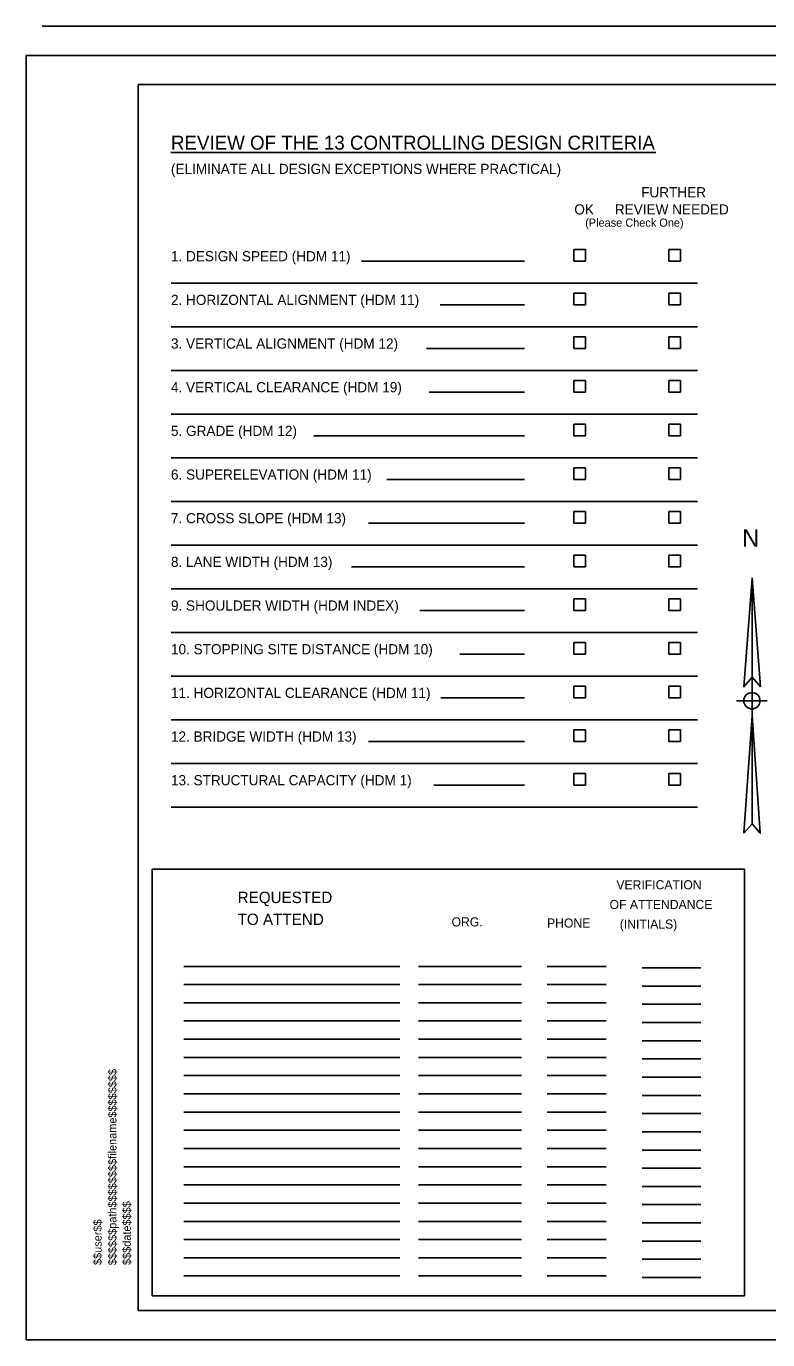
# Model space of a CAD drawing. Extents: x -796 to 2793, y -4650 to 4425.
# Drawn here: x 986 to 1622, y 2150 to 3275 of the extents above; entities that cross this region are included whole.
import ezdxf

# ---------------------------------------------------------------- set-up
doc = ezdxf.new("R2010")
doc.units = 0
for name, color, linetype in [('RD_EX_Misc', 7, 'Continuous'), ('RD_HC_CL', 7, 'Continuous'), ('RD_HC_Data', 7, 'Continuous'), ('RD_HC_Data_Tic', 7, 'Continuous'), ('RD_TX_Misc1', 7, 'Continuous')]:
    doc.layers.add(name, color=color, linetype=linetype)

msp = doc.modelspace()

# ---------------------------------------------------------------- linework, layer by layer
at = {"layer": 'RD_EX_Misc'}
for p, q in [((1608.2, 2802.4), (1601.2, 2709.1)), ((1608.2, 2802.4), (1615.4, 2709.1)), ((1608.2, 2802.4), (1608.2, 2591.7)), ((1608.2, 2717.6), (1601.2, 2709.1)), ((1608.2, 2717.6), (1615.4, 2709.1)), ((1594.9, 2697.3), (1621.3, 2697.3)), ((1608.2, 2684.7), (1601.3, 2583.8)), ((1608.2, 2684.7), (1615.3, 2583.8)), ((1601.3, 2583.8), (1608.2, 2591.9)), ((1615.3, 2583.8), (1608.2, 2591.9))]:
    msp.add_line(p, q, dxfattribs=at)
for points in [[(1608.2, 2717.6), (1608.2, 2802.4), (1601.2, 2709.1), (1608.2, 2717.6)], [(1608.2, 2697.3), (1608.2, 2704.3)], [(1601.1, 2697.3), (1608.2, 2697.3)], [(1608.2, 2697.3), (1608.2, 2690.3)], [(1615.1, 2697.3), (1608.2, 2697.3)], [(1608.2, 2684.7), (1608.2, 2591.8), (1608.2, 2591.9), (1615.3, 2583.8), (1608.2, 2684.7)]]:
    msp.add_lwpolyline(points, dxfattribs=at)
for start, end in [(89.5907, 180), (89.5907, 180), (0, 89.5907), (180, 270.4093), (270.4093, 0), (270.4093, 0)]:
    msp.add_arc((1608.1, 2697.3), 7, start, end, dxfattribs=at)
at = {"layer": 'RD_HC_CL'}
msp.add_lwpolyline([(986.4, 3250), (2782.4, 3250), (2782.4, 2150), (986.4, 2150)], close=True, dxfattribs=at)
at = {"layer": 'RD_HC_Data'}
for p, q in [((2760, 3275), (1000, 3275)), ((2760, 3275), (1000, 3275)), ((2760, 3250), (1000, 3250)), ((1525.9, 3166.8), (1110.2, 3166.8)), ((1465.5, 3083.7), (1455.5, 3083.7)), ((1455.5, 3073.7), (1455.5, 3083.7)), ((1465.5, 3073.7), (1465.5, 3083.7)), ((1547, 3083.7), (1537, 3083.7)), ((1537, 3073.7), (1537, 3083.7)), ((1547, 3073.7), (1547, 3083.7)), ((1413.3, 3073.7), (1273.7, 3073.7)), ((1465.5, 3073.7), (1455.5, 3073.7)), ((1547, 3073.7), (1537, 3073.7)), ((1561.4, 3055), (1110.7, 3055)), ((1465.5, 3046.3), (1455.5, 3046.3)), ((1455.5, 3036.3), (1455.5, 3046.3)), ((1465.5, 3036.3), (1465.5, 3046.3)), ((1547, 3046.3), (1537, 3046.3)), ((1537, 3046.3), (1537, 3036.3)), ((1547, 3046.3), (1547, 3036.3)), ((1413.3, 3036.3), (1340.9, 3036.3)), ((1465.5, 3036.3), (1455.5, 3036.3)), ((1547, 3036.3), (1537, 3036.3)), ((1561.4, 3017.6), (1110.7, 3017.6)), ((1465.5, 3008.9), (1455.5, 3008.9)), ((1455.5, 2998.9), (1455.5, 3008.9)), ((1465.5, 3008.9), (1465.5, 2998.9)), ((1547, 3008.9), (1537, 3008.9)), ((1537, 3008.9), (1537, 2998.9)), ((1547, 2998.9), (1547, 3008.9)), ((1413.3, 2998.9), (1329.3, 2998.9)), ((1465.5, 2998.9), (1455.5, 2998.9)), ((1547, 2998.9), (1537, 2998.9)), ((1561.4, 2980.2), (1110.7, 2980.2)), ((1465.5, 2971.5), (1455.5, 2971.5)), ((1455.5, 2971.5), (1455.5, 2961.5)), ((1465.5, 2961.5), (1465.5, 2971.5)), ((1547, 2971.5), (1537, 2971.5)), ((1537, 2971.5), (1537, 2961.5)), ((1547, 2971.5), (1547, 2961.5)), ((1413.3, 2961.5), (1331.7, 2961.5)), ((1465.5, 2961.5), (1455.5, 2961.5)), ((1547, 2961.5), (1537, 2961.5)), ((1561.4, 2942.8), (1110.7, 2942.8)), ((1465.5, 2934.1), (1455.5, 2934.1)), ((1455.5, 2934.1), (1455.5, 2924.1)), ((1465.5, 2924.1), (1465.5, 2934.1)), ((1547, 2934.1), (1537, 2934.1)), ((1537, 2934.1), (1537, 2924.1)), ((1547, 2934.1), (1547, 2924.1)), ((1413.3, 2924.1), (1232.7, 2924.1)), ((1465.5, 2924.1), (1455.5, 2924.1)), ((1547, 2924.1), (1537, 2924.1)), ((1561.4, 2905.4), (1110.7, 2905.4)), ((1465.5, 2896.7), (1455.5, 2896.7)), ((1455.5, 2896.7), (1455.5, 2886.7)), ((1465.5, 2886.7), (1465.5, 2896.7)), ((1547, 2896.7), (1537, 2896.7)), ((1537, 2896.7), (1537, 2886.7)), ((1547, 2896.7), (1547, 2886.7)), ((1413.3, 2886.7), (1295.4, 2886.7)), ((1465.5, 2886.7), (1455.5, 2886.7)), ((1547, 2886.7), (1537, 2886.7)), ((1561.4, 2868), (1110.7, 2868)), ((1465.5, 2859.3), (1455.5, 2859.3)), ((1455.5, 2859.3), (1455.5, 2849.3)), ((1465.5, 2849.3), (1465.5, 2859.3)), ((1547, 2859.3), (1537, 2859.3)), ((1537, 2859.3), (1537, 2849.3)), ((1547, 2859.3), (1547, 2849.3)), ((1413.3, 2849.3), (1279.6, 2849.3)), ((1465.5, 2849.3), (1455.5, 2849.3)), ((1547, 2849.3), (1537, 2849.3)), ((1561.4, 2830.6), (1110.7, 2830.6)), ((1465.5, 2821.9), (1455.5, 2821.9)), ((1455.5, 2821.9), (1455.5, 2811.9)), ((1465.5, 2811.9), (1465.5, 2821.9)), ((1547, 2821.9), (1537, 2821.9)), ((1537, 2821.9), (1537, 2811.9)), ((1547, 2821.9), (1547, 2811.9)), ((1413.3, 2811.9), (1265.2, 2811.9)), ((1465.5, 2811.9), (1455.5, 2811.9)), ((1547, 2811.9), (1537, 2811.9)), ((1561.4, 2793.2), (1110.7, 2793.2)), ((1465.5, 2784.5), (1455.5, 2784.5)), ((1455.5, 2774.5), (1455.5, 2784.5)), ((1465.5, 2784.5), (1465.5, 2774.5)), ((1547, 2784.5), (1537, 2784.5)), ((1537, 2774.5), (1537, 2784.5)), ((1547, 2784.5), (1547, 2774.5)), ((1413.3, 2774.5), (1323.5, 2774.5)), ((1465.5, 2774.5), (1455.5, 2774.5)), ((1547, 2774.5), (1537, 2774.5)), ((1561.4, 2755.8), (1110.7, 2755.8)), ((1465.5, 2747.1), (1455.5, 2747.1)), ((1455.5, 2747.1), (1455.5, 2737.1)), ((1465.5, 2737.1), (1465.5, 2747.1)), ((1547, 2747.1), (1537, 2747.1)), ((1537, 2747.1), (1537, 2737.1)), ((1547, 2737.1), (1547, 2747.1)), ((1413.3, 2737.1), (1358, 2737.1)), ((1465.5, 2737.1), (1455.5, 2737.1)), ((1547, 2737.1), (1537, 2737.1)), ((1561.4, 2718.4), (1110.7, 2718.4)), ((1465.5, 2709.7), (1455.5, 2709.7)), ((1455.5, 2709.7), (1455.5, 2699.7)), ((1465.5, 2699.7), (1465.5, 2709.7)), ((1547, 2709.7), (1537, 2709.7)), ((1537, 2709.7), (1537, 2699.7)), ((1547, 2699.7), (1547, 2709.7)), ((1413.3, 2699.7), (1341.5, 2699.7)), ((1465.5, 2699.7), (1455.5, 2699.7)), ((1547, 2699.7), (1537, 2699.7)), ((1561.4, 2681), (1110.7, 2681)), ((1465.5, 2672.3), (1455.5, 2672.3)), ((1455.5, 2672.3), (1455.5, 2662.3)), ((1465.5, 2662.3), (1465.5, 2672.3)), ((1547, 2672.3), (1537, 2672.3)), ((1537, 2672.3), (1537, 2662.3)), ((1547, 2662.3), (1547, 2672.3)), ((1413.3, 2662.3), (1279.6, 2662.3)), ((1465.5, 2662.3), (1455.5, 2662.3)), ((1547, 2662.3), (1537, 2662.3)), ((1561.4, 2643.6), (1110.7, 2643.6)), ((1465.5, 2634.9), (1455.5, 2634.9)), ((1455.5, 2634.9), (1455.5, 2624.9)), ((1465.5, 2624.9), (1465.5, 2634.9)), ((1547, 2634.9), (1537, 2634.9)), ((1537, 2634.9), (1537, 2624.9)), ((1547, 2624.9), (1547, 2634.9)), ((1413.3, 2624.9), (1335.7, 2624.9)), ((1465.5, 2624.9), (1455.5, 2624.9)), ((1547, 2624.9), (1537, 2624.9)), ((1561.4, 2606.2), (1110.7, 2606.2)), ((1121.3, 2469.8), (1306.4, 2469.8)), ((1322.4, 2469.8), (1410.6, 2469.8)), ((1432.8, 2469.8), (1483.2, 2469.8)), ((1514.1, 2468.5), (1564.4, 2468.5)), ((1121.3, 2454.2), (1306.4, 2454.2)), ((1322.4, 2454.2), (1410.6, 2454.2)), ((1432.8, 2454.2), (1483.2, 2454.2)), ((1514.1, 2452.9), (1564.4, 2452.9)), ((1121.3, 2438.6), (1306.4, 2438.6)), ((1322.4, 2438.6), (1410.6, 2438.6)), ((1432.8, 2438.6), (1483.2, 2438.6)), ((1514.1, 2437.3), (1564.4, 2437.3)), ((1121.3, 2423), (1306.4, 2423)), ((1322.4, 2423), (1410.6, 2423)), ((1432.8, 2423), (1483.2, 2423)), ((1514.1, 2421.7), (1564.4, 2421.7)), ((1121.3, 2407.4), (1306.4, 2407.4)), ((1322.4, 2407.4), (1410.6, 2407.4)), ((1432.8, 2407.4), (1483.2, 2407.4)), ((1514.1, 2406.1), (1564.4, 2406.1)), ((1121.3, 2391.8), (1306.4, 2391.8)), ((1322.4, 2391.8), (1410.6, 2391.8)), ((1432.8, 2391.8), (1483.2, 2391.8)), ((1514.1, 2390.5), (1564.4, 2390.5)), ((1121.3, 2376.2), (1306.4, 2376.2)), ((1322.4, 2376.2), (1410.6, 2376.2)), ((1432.8, 2376.2), (1483.2, 2376.2)), ((1514.1, 2374.9), (1564.4, 2374.9)), ((1121.3, 2360.6), (1306.4, 2360.6)), ((1322.4, 2360.6), (1410.6, 2360.6)), ((1432.8, 2360.6), (1483.2, 2360.6)), ((1514.1, 2359.3), (1564.4, 2359.3)), ((1121.3, 2345), (1306.4, 2345)), ((1322.4, 2345), (1410.6, 2345)), ((1432.8, 2345), (1483.2, 2345)), ((1514.1, 2343.7), (1564.4, 2343.7)), ((1121.3, 2329.4), (1306.4, 2329.4)), ((1322.4, 2329.4), (1410.6, 2329.4)), ((1432.8, 2329.4), (1483.2, 2329.4)), ((1514.1, 2328.1), (1564.4, 2328.1)), ((1121.3, 2313.8), (1306.4, 2313.8)), ((1322.4, 2313.8), (1410.6, 2313.8)), ((1432.8, 2313.8), (1483.2, 2313.8)), ((1514.1, 2312.5), (1564.4, 2312.5)), ((1121.3, 2298.2), (1306.4, 2298.2)), ((1322.4, 2298.2), (1410.6, 2298.2)), ((1432.8, 2298.2), (1483.2, 2298.2)), ((1514.1, 2296.9), (1564.4, 2296.9)), ((1121.3, 2282.6), (1306.4, 2282.6)), ((1322.4, 2282.6), (1410.6, 2282.6)), ((1432.8, 2282.6), (1483.2, 2282.6)), ((1514.1, 2281.3), (1564.4, 2281.3)), ((1121.3, 2267), (1306.4, 2267)), ((1322.4, 2267), (1410.6, 2267)), ((1432.8, 2267), (1483.2, 2267)), ((1514.1, 2265.7), (1564.4, 2265.7)), ((1121.3, 2251.4), (1306.4, 2251.4)), ((1322.4, 2251.4), (1410.6, 2251.4)), ((1432.8, 2251.4), (1483.2, 2251.4)), ((1514.1, 2250.1), (1564.4, 2250.1)), ((1121.3, 2235.8), (1306.4, 2235.8)), ((1322.4, 2235.8), (1410.6, 2235.8)), ((1432.8, 2235.8), (1483.2, 2235.8)), ((1514.1, 2234.5), (1564.4, 2234.5)), ((1121.3, 2220.2), (1306.4, 2220.2)), ((1322.4, 2220.2), (1410.6, 2220.2)), ((1432.8, 2220.2), (1483.2, 2220.2)), ((1514.1, 2218.9), (1564.4, 2218.9)), ((1121.3, 2204.6), (1306.4, 2204.6)), ((1322.4, 2204.6), (1410.6, 2204.6)), ((1432.8, 2204.6), (1483.2, 2204.6)), ((1514.1, 2203.3), (1564.4, 2203.3)), ((2760, 2150), (1000, 2150))]:
    msp.add_line(p, q, dxfattribs=at)
for points in [[(1082.4, 3225), (2757.4, 3225), (2757.4, 2175), (1082.4, 2175)], [(1094.2, 2553), (1094.2, 2187.6), (1601.7, 2187.6), (1601.7, 2553)]]:
    msp.add_lwpolyline(points, close=True, dxfattribs=at)

# ---------------------------------------------------------------- texts
at = {"layer": 'RD_EX_Misc'}
msp.add_text('N', height=15, dxfattribs=at).set_placement((1599.8, 2829.2))
at = {"layer": 'RD_HC_Data_Tic'}
for s, height, p in [('REVIEW OF THE 13 CONTROLLING DESIGN CRITERIA', 12, (1110.4, 3169.3)), ('(ELIMINATE ALL DESIGN EXCEPTIONS WHERE PRACTICAL)', 8.7, (1110.4, 3148.5)), ('FURTHER', 8.7, (1513.2, 3128.5)), ('OK', 8.7, (1456, 3113.8)), ('REVIEW NEEDED', 8.7, (1490.7, 3113.8)), ('(Please Check One)', 7, (1465.3, 3103.3)), ('1. DESIGN SPEED (HDM 11)', 8.7, (1110.4, 3073.7)), ('2. HORIZONTAL ALIGNMENT (HDM 11)', 8.7, (1110.4, 3036.3)), ('3. VERTICAL ALIGNMENT (HDM 12)', 8.7, (1110.4, 2998.9)), ('4. VERTICAL CLEARANCE (HDM 19)', 8.7, (1110.4, 2961.5)), ('5. GRADE (HDM 12)', 8.7, (1110.4, 2924.1)), ('6. SUPERELEVATION (HDM 11)', 8.7, (1110.4, 2886.7)), ('7. CROSS SLOPE (HDM 13)', 8.7, (1110.4, 2849.3)), ('8. LANE WIDTH (HDM 13)', 8.7, (1110.4, 2811.9)), ('9. SHOULDER WIDTH (HDM INDEX)', 8.7, (1110.4, 2774.5)), ('10. STOPPING SITE DISTANCE (HDM 10)', 8.7, (1110.4, 2737.1)), ('11. HORIZONTAL CLEARANCE (HDM 11)', 8.7, (1110.4, 2699.7)), ('12. BRIDGE WIDTH (HDM 13)', 8.7, (1110.4, 2662.3)), ('13. STRUCTURAL CAPACITY (HDM 1)', 8.7, (1110.4, 2624.9)), ('  VERIFICATION ', 7.8, (1486.2, 2535.8)), ('REQUESTED ', 9.75, (1167.5, 2524)), ('OF ATTENDANCE', 7.8, (1486.2, 2518.9)), ('TO ATTEND', 9.75, (1167.5, 2505.2)), ('ORG.', 7.8, (1350.8, 2504)), ('PHONE', 7.8, (1432.6, 2503)), ('   (INITIALS)', 7.8, (1486.2, 2502.1))]:
    msp.add_text(s, height=height, dxfattribs=at).set_placement(p)
at = {"layer": 'RD_TX_Misc1'}
for s, p in [('$$$$$$path$$$$$$$$filename$$$$$$$$', (1063.7, 2213.8)), ('$$$date$$$$', (1076, 2214)), ('$$user$$', (1051, 2214))]:
    msp.add_text(s, height=7, rotation=90, dxfattribs=at).set_placement(p)

doc.saveas('drawing.dxf')
